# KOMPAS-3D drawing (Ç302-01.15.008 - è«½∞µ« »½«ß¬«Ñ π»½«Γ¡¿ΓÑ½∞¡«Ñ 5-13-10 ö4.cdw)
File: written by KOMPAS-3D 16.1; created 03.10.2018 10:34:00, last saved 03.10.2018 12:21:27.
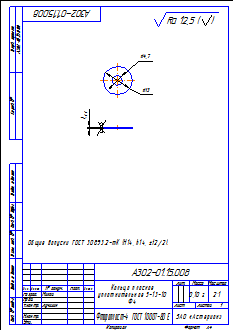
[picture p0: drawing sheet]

Sheet 1: A4, portrait

Title block, sheet 1: name: Кольцо плоское / уплотнительное 5-13-10 / Ф4; designation: А302-01.15.008; material: Фторопласт-4  ГОСТ 10007-80 Е; mass: 0,10 г; scale: 2:1; sheets: 1; organisation: ЗАО «Астерион»; sheet format: A4; stored path: \\192.168.87.28\Konstructor_doc\Мембранные насосы\Мембранный электропривод\А302-00.00.000 - ASTRA-302 (МЭ200)\3Д ПВХ\А302-01.15.008 - Кольцо плоское уплотнительное 5-13-10 Ф4.cdw; drawn by: Милов; technical control: Лучихин

Views: Вид 1, Спереди, Проекционный вид 2
Referenced files in Z:\Мембранные насосы\Мембранный электропривод\А302-00.00.000 - ASTRA-302 (МЭ200)\3Д ПВХ\: А302-01.15.008 - Кольцо плоское Ф4.m3d
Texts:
  Общие допуски ГОСТ 30893.2-mK (H14, h14,  t2/2).
  Ra 12,5
  Ra 12,5 ( )
Dimensions and other numbers on the sheet: 4,7; 13; 1; 2:1; 0,10 г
